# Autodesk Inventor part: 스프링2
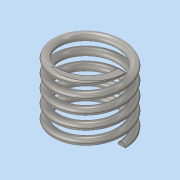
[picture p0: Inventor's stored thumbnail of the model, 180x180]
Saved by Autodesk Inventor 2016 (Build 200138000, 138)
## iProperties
Created: 2019-11
Part Number: 스프링2
Material: 스테인레스 스틸
Document SubType Name: Modeling
Designer: user
Density: 8 g/cm^3
Appearance: 반연마
Mass: 6.54897 g
Surface Area: 16.6959 cm^2
Volume: 0.818622 cm^3
Author: user
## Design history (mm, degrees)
sketch "스케치1"
  geometry: L1 (0, 0)-(8.5, 0); L2 (8.5, 0)-(8.5, 17.5); L3 (8.5, 17.5)-(0, 17.5); L4 (0, 17.5)-(0, 0); C1 r 1 at (8.5, 0)
  constraints: 8 end point, 2 parallel, 1 centre point, 1 coincident, 1 horizontal, 1 perpendicular
  dimensions: "d0" = 17 diameter of L2 L4; "d1" = 17.5 distance between parallel lines of L1 L3 (derived); "d2" = 2 diameter of C1
feature "코일1" sketch "스케치1" pitch "d3" = 10; turns "d5" = 5; dims "d4" = 17.5 (= d1), "d6" = 0, angle "d7" = 90 deg, angle "d8" = 90 deg, "d9" = 0, "d10" = 0
sketch "스케치2"
  geometry: L1 (17.5, 11.695)-(0, 11.695); L2 (0, 11.695)-(0, -11.695); L3 (0, -11.695)-(17.5, -11.695); L4 (17.5, -11.695)-(17.5, 11.695); 2 further points
  constraints: 8 end point, 2 parallel, 1 coincident, 1 horizontal, 1 midpoint, 1 perpendicular
  dimensions: "d11" = 17.5 distance between parallel lines of L2 L4 (= d1)
extrude "돌출1" sketch "스케치2" stored distance "d12" = 42; taper "d13" = 0 deg
node "솔리드1"
